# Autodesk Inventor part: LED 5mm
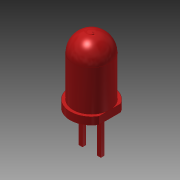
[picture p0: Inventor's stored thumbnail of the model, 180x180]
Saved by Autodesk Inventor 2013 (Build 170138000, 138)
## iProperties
Created: 2012-08
Part Number: LED 5mm
Material: PC/ABS-Kunststoff
Document SubType Name: Modeling
Designer: rYan
Density: 1.493 g/cm^3
Mass: 0.251708 g
Surface Area: 1.94358 cm^2
Volume: 0.168592 cm^3
Author: rYan
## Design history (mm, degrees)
sketch "Skizze1"
  geometry: L1 (0, 0)-(0, 9); L2 (0, 0)-(2.9, 0); L3 (2.9, 0)-(2.9, 1); L4 (2.9, 1)-(2.5, 1); L5 (2.5, 1)-(2.5, 6.5); A1 r 2.5 centre (0, 6.5) between (2.5, 6.5) and (0, 9)
  constraints: 10 end point, 2 parallel, 2 perpendicular, 2 point on circle, 1 centre point, 1 point on line, 1 tangent, 1 vertical
  dimensions: "d0" = 5.8 diameter of L3 L1; "d2" = 5 diameter of L5 L1; "d3" = 9 distance of L1.start L1.end; "d4" = 1 distance of L2.end L3.end
revolve "Umdrehung1" sketch "Skizze1" stored, may be unused: angle "d5" = 90 deg
workplane "Arbeitsebene2"
sketch "Skizze2"
  geometry: L1 (-2.9, -3.75)-(2.9, -3.75) reference; L2 (-2.9, -2.75)-(2.9, -2.75) reference; L3 (-2.9, -2.75)-(2.9, -2.75); L4 (2.9, -2.75)-(2.9, -3.75); L5 (2.9, -3.75)-(-2.9, -3.75); L6 (-2.9, -3.75)-(-2.9, -2.75); 1 further point
  constraints: 8 end point, 2 parallel, 1 horizontal, 1 perpendicular
extrude "Extrusion1" cut sketch "Skizze2" distance "d6" = 1; taper "d7" = 0 deg
sketch "Skizze3"
  geometry: L1 (-1.5, 0.225)-(-1, 0.225); L2 (-1, 0.225)-(-1, -0.225); L3 (-1, -0.225)-(-1.5, -0.225); L4 (-1.5, -0.225)-(-1.5, 0.225); L5 (1, 0.225)-(1.5, 0.225); L6 (1.5, 0.225)-(1.5, -0.225); L7 (1.5, -0.225)-(1, -0.225); L8 (1, -0.225)-(1, 0.225); L9 (0, -4.06)-(0, 4.06) reference; L10 (-3.58, 0)-(3.98, 0) reference; 1 further point
  constraints: 16 end point, 4 parallel, 2 horizontal, 2 perpendicular, 5 other
  dimensions: "d8" = 0.5 distance of L1.start L1.end; "d10" = 0.45 distance of L1.end L2.end; "d11" = 3 distance between parallel lines of L6 L4
extrude "Extrusion2" join sketch "Skizze3" distance "d12" = 5; taper "d13" = 0 deg
node "Volumenkörper1"
node "Projizierte Kontur1"
